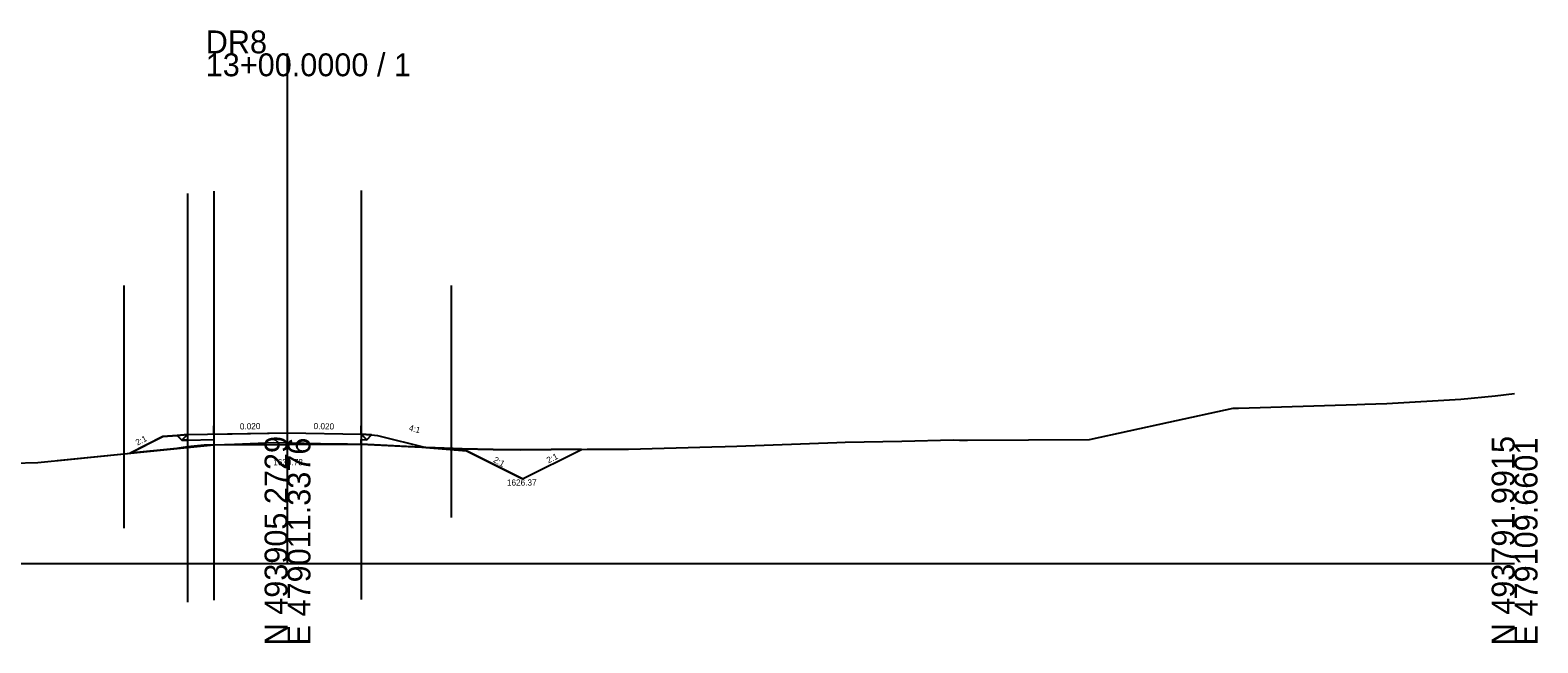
# Model space of a CAD drawing. Extents: x 24 to 353, y -10 to 3552.
# Drawn here: x 168.5 to 352.8, y 2990.3 to 3065.2 of the extents above; entities that cross this region are included whole.
import ezdxf

# ---------------------------------------------------------------- set-up
doc = ezdxf.new("R2010")
doc.units = 0
for name, color, linetype in [('Exist Cross Section Cell', 7, 'Continuous'), ('Exist XS Center Line Elevation Label', 7, 'Continuous'), ('Exist XS Ground Line', 7, 'Continuous'), ('Prop XS DDE', 7, 'Continuous'), ('Prop XS DDE Earthwork Shape', 7, 'Continuous'), ('Prop XS DDE Elevations', 7, 'Continuous'), ('Prop XS DDE Slope Text', 7, 'Continuous'), ('Prop XS Ditch Slope Text', 7, 'Continuous'), ('Prop XS Dump Level', 7, 'Continuous'), ('Prop XS Earthwork Shape', 7, 'Continuous'), ('Prop XS EOT Tick Mark', 7, 'Continuous'), ('Prop XS Finish Grade', 7, 'Continuous'), ('Prop XS Finish Grade Earthwork', 7, 'Continuous'), ('Prop XS Finish Grade Pavement', 7, 'Continuous'), ('Prop XS Hydro Typical Ditch Data', 7, 'Continuous'), ('Prop XS Pvmt Edge Slope', 7, 'Continuous'), ('Prop XS SE Text', 7, 'Continuous'), ('Prop XS Shoulder Borrow Shape', 7, 'Continuous'), ('Prop XS Side Slope Text', 7, 'Continuous'), ('Prop XS Subgrade Earthwork', 7, 'Continuous'), ('Scratch_Level_1', 7, 'Continuous'), ('Scratch_Level_4', 7, 'Continuous'), ('Scratch_Level_5', 7, 'Continuous'), ('Scratch_Level_6', 7, 'Continuous')]:
    doc.layers.add(name, color=color, linetype=linetype)

msp = doc.modelspace()

# ---------------------------------------------------------------- linework, layer by layer
at = {"layer": 'Exist Cross Section Cell'}
for p, q in [((200, 3000), (200, 3062.4)), ((50, 3000), (200, 3000)), ((200, 3000), (350, 3000))]:
    msp.add_line(p, q, dxfattribs=at)
at = {"layer": 'Exist XS Ground Line'}
msp.add_lwpolyline([(166.43, 3012.29), (169.49, 3012.36), (173.59, 3012.78), (186.47, 3014.08), (187.76, 3014.27), (189.82, 3014.49), (193.53, 3014.62), (198.34, 3014.81), (200, 3014.78), (206.05, 3014.66), (207.34, 3014.63), (209, 3014.61), (218.06, 3014.14), (221.35, 3014.05), (225.15, 3013.97), (228.45, 3013.93), (232.24, 3013.97), (236.61, 3013.98), (241.69, 3014), (251.87, 3014.27), (253.51, 3014.34), (254.94, 3014.36), (267.13, 3014.81), (268.18, 3014.84), (275.09, 3014.99), (281.42, 3015.12), (282.16, 3015.1), (283.11, 3015.1), (298.05, 3015.18), (307.75, 3017.31), (315.59, 3018.99), (316.24, 3018.99), (330.71, 3019.45), (331.7, 3019.48), (334.4, 3019.57), (343.42, 3020.13), (347.64, 3020.5), (350, 3020.8)], dxfattribs=at)
at = {"layer": 'Prop XS DDE'}
for p, q in [((221.89, 3013.78), (216.89, 3014.2)), ((228.72, 3010.37), (221.89, 3013.78)), ((228.72, 3010.37), (235.93, 3013.97))]:
    msp.add_line(p, q, dxfattribs=at)
at = {"layer": 'Prop XS DDE Earthwork Shape'}
for p, q in [((216.89, 3014.2), (221.89, 3013.78)), ((221.89, 3013.78), (228.72, 3010.37)), ((228.72, 3010.37), (235.93, 3013.97)), ((235.93, 3013.97), (232.24, 3013.97))]:
    msp.add_line(p, q, dxfattribs=at)
msp.add_lwpolyline([(232.24, 3013.97), (228.45, 3013.93), (225.15, 3013.97), (221.35, 3014.05), (218.06, 3014.14), (216.89, 3014.2)], dxfattribs=at)
at = {"layer": 'Prop XS Dump Level'}
for p, q in [((191, 3015.83), (200, 3016.01)), ((200, 3016.01), (209, 3015.83))]:
    msp.add_line(p, q, dxfattribs=at)
at = {"layer": 'Prop XS Earthwork Shape'}
for points in [[(187.77, 3015.1), (191, 3015.17), (191, 3014.53), (189.82, 3014.49), (187.76, 3014.27), (186.47, 3014.08), (180.71, 3013.5), (184.77, 3015.53), (186.51, 3015.67), (187.09, 3015.09)], [(210.26, 3015.73), (211, 3015.67), (216.89, 3014.2), (209, 3014.61), (209, 3015.17), (209.68, 3015.15)]]:
    msp.add_lwpolyline(points, close=True, dxfattribs=at)
at = {"layer": 'Prop XS EOT Tick Mark'}
for p, q in [((191, 3015.83), (191, 3016.83)), ((209, 3015.83), (209, 3016.83))]:
    msp.add_line(p, q, dxfattribs=at)
at = {"layer": 'Prop XS Finish Grade'}
for p, q in [((187.77, 3015.77), (186.51, 3015.67)), ((209, 3015.83), (210.26, 3015.73))]:
    msp.add_line(p, q, dxfattribs=at)
at = {"layer": 'Prop XS Finish Grade Earthwork'}
for p, q in [((184.77, 3015.53), (180.76, 3013.52)), ((186.51, 3015.67), (184.77, 3015.53)), ((210.26, 3015.73), (211, 3015.67)), ((211, 3015.67), (216.89, 3014.2))]:
    msp.add_line(p, q, dxfattribs=at)
at = {"layer": 'Prop XS Finish Grade Pavement'}
for p, q in [((187.77, 3015.77), (200, 3016.01)), ((200, 3016.01), (209, 3015.83))]:
    msp.add_line(p, q, dxfattribs=at)
at = {"layer": 'Prop XS Hydro Typical Ditch Data'}
msp.add_line((211, 3015.67), (216.89, 3014.2), dxfattribs=at)
at = {"layer": 'Prop XS Pvmt Edge Slope'}
for p, q in [((187.77, 3015.77), (187.09, 3015.09)), ((209, 3015.83), (209.68, 3015.15))]:
    msp.add_line(p, q, dxfattribs=at)
at = {"layer": 'Prop XS Shoulder Borrow Shape'}
for points in [[(187.77, 3015.77), (187.09, 3015.09), (186.51, 3015.67)], [(187.77, 3015.77), (187.09, 3015.09), (186.51, 3015.67)], [(187.77, 3015.77), (187.09, 3015.09), (186.51, 3015.67)], [(209.68, 3015.15), (210.26, 3015.73), (209, 3015.83)], [(209.68, 3015.15), (210.26, 3015.73), (209, 3015.83)], [(209.68, 3015.15), (210.26, 3015.73), (209, 3015.83)]]:
    msp.add_lwpolyline(points, close=True, dxfattribs=at)
at = {"layer": 'Prop XS Subgrade Earthwork'}
for p, q in [((187.09, 3015.09), (186.51, 3015.67)), ((209.68, 3015.15), (210.26, 3015.73)), ((187.77, 3015.1), (187.09, 3015.09)), ((187.77, 3015.1), (191, 3015.17)), ((191, 3015.17), (191, 3014.53)), ((209, 3015.17), (209.68, 3015.15)), ((209, 3015.17), (209, 3014.61))]:
    msp.add_line(p, q, dxfattribs=at)
at = {"layer": 'Scratch_Level_1'}
for p, q in [((180, 3034), (180, 3004.34)), ((220, 3034), (220, 3005.62))]:
    msp.add_line(p, q, dxfattribs=at)
at = {"layer": 'Scratch_Level_4'}
msp.add_line((171.82, 3012.6), (191, 3014.53), dxfattribs=at)
at = {"layer": 'Scratch_Level_5'}
for p, q in [((187.77, 3045.27), (187.77, 2995.27)), ((191, 3045.53), (191, 2995.53)), ((209, 3045.61), (209, 2995.61))]:
    msp.add_line(p, q, dxfattribs=at)
msp.add_lwpolyline([(166.43, 3012.29), (169.49, 3012.36), (173.59, 3012.78), (186.47, 3014.08), (187.76, 3014.27), (189.82, 3014.49), (193.53, 3014.62), (198.34, 3014.81), (200, 3014.78), (206.05, 3014.66), (207.34, 3014.63), (209, 3014.61), (218.06, 3014.14), (221.35, 3014.05), (225.15, 3013.97), (228.45, 3013.93), (232.24, 3013.97), (236.61, 3013.98), (241.69, 3014), (251.87, 3014.27), (253.51, 3014.34), (254.94, 3014.36), (267.13, 3014.81), (268.18, 3014.84), (275.09, 3014.99), (281.42, 3015.12), (282.16, 3015.1), (283.11, 3015.1), (298.05, 3015.18), (307.75, 3017.31), (315.59, 3018.99), (316.24, 3018.99), (330.71, 3019.45), (331.7, 3019.48), (334.4, 3019.57), (343.42, 3020.13), (347.64, 3020.5), (350, 3020.8)], dxfattribs=at)
at = {"layer": 'Scratch_Level_6'}
msp.add_line((191, 3014.53), (209, 3014.61), dxfattribs=at)

# ---------------------------------------------------------------- texts
at = {"layer": 'Exist Cross Section Cell'}
for s, p in [('DR8', (190, 3062.4)), ('13+00.0000 / 1', (190, 3059.6))]:
    msp.add_text(s, height=2.8, dxfattribs=at).set_placement(p)
for s, p in [('N 493905.2729', (200, 2990)), ('E 479011.3376', (202.8, 2990)), ('N 493791.9915', (350, 2990)), ('E 479109.6601', (352.8, 2990))]:
    msp.add_text(s, height=2.8, rotation=90, dxfattribs=at).set_placement(p)
at = {"layer": 'Exist XS Center Line Elevation Label'}
msp.add_text('1630.78', height=0.75, dxfattribs=at).set_placement((198.25, 3012.03))
at = {"layer": 'Prop XS DDE Elevations'}
msp.add_text('1626.37', height=0.75, dxfattribs=at).set_placement((226.82, 3009.54))
at = {"layer": 'Prop XS DDE Slope Text'}
for rotation, p in [(26.5651, (231.89, 3012.24)), (331.0921, (225.07, 3012.47))]:
    msp.add_text('2:1', height=0.75, rotation=rotation, dxfattribs=at).set_placement(p)
at = {"layer": 'Prop XS Ditch Slope Text'}
msp.add_text('4:1', height=0.75, rotation=345.9638, dxfattribs=at).set_placement((214.78, 3016.27))
at = {"layer": 'Prop XS Dump Level'}
for p in [(189, 3015.63), (211, 3015.63)]:
    msp.add_text('Case1', height=0.04, dxfattribs=at).set_placement(p)
at = {"layer": 'Prop XS SE Text'}
for rotation, p in [(1.1458, (194.18, 3016.4)), (358.8542, (203.18, 3016.45))]:
    msp.add_text('0.020', height=0.75, rotation=rotation, dxfattribs=at).set_placement(p)
at = {"layer": 'Prop XS Side Slope Text'}
msp.add_text('2:1', height=0.75, rotation=26.5651, dxfattribs=at).set_placement((181.65, 3014.42))

doc.saveas('drawing.dxf')
